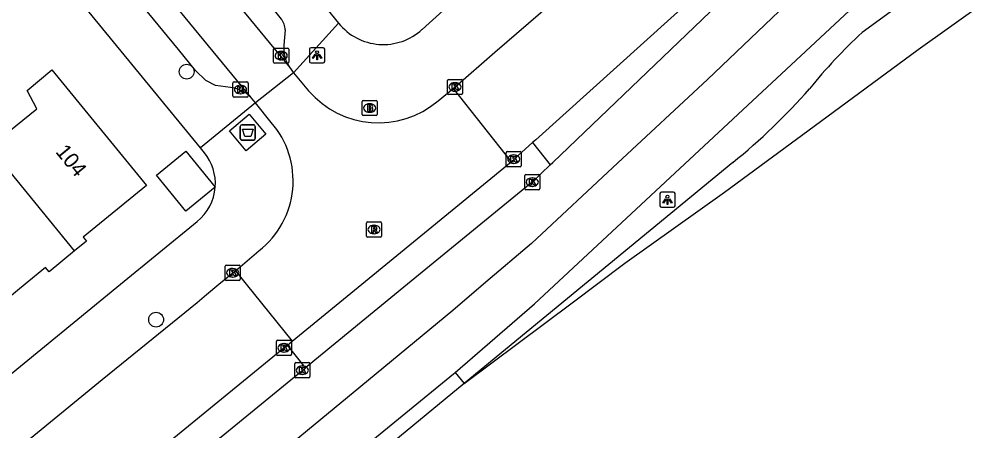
# Model space of a CAD drawing. Extents: x 162074 to 163034, y 381824 to 382557.
# Drawn here: x 162697.9 to 162760.7, y 381990.3 to 382017.5 of the extents above; entities that cross this region are included whole.
import ezdxf

# ---------------------------------------------------------------- set-up
doc = ezdxf.new("R2010")
doc.units = 0
for name, color, linetype in [('IMGEO_Afval_apart_plaats', 7, 'Continuous'), ('IMGEO_Berm_gesloten', 7, 'Continuous'), ('IMGEO_Boom', 7, 'Continuous'), ('IMGEO_Brandkraan', 7, 'Continuous'), ('IMGEO_Haag', 7, 'Continuous'), ('IMGEO_Kolk', 7, 'Continuous'), ('IMGEO_Lichtpunt', 7, 'Continuous'), ('IMGEO_Pand', 7, 'Continuous'), ('IMGEO_Pand_nummerreeks', 7, 'Continuous'), ('IMGEO_Rijbaan_lokaal_open', 7, 'Continuous'), ('IMGEO_Rijbaan_regionaal_gesloten', 7, 'Continuous'), ('IMGEO_Rioolput', 7, 'Continuous'), ('IMGEO_Voetpad_gesloten', 7, 'Continuous'), ('IMGEO_Voetpad_open', 7, 'Continuous')]:
    doc.layers.add(name, color=color, linetype=linetype)

msp = doc.modelspace()

# ---------------------------------------------------------------- linework, layer by layer
at = {"layer": 'IMGEO_Afval_apart_plaats'}
for p, q in [((162712.524, 382009.61), (162712.524, 382010.41)), ((162712.524, 382010.41), (162712.524, 382009.61)), ((162712.624, 382010.51), (162713.414, 382010.51)), ((162713.414, 382010.51), (162712.624, 382010.51)), ((162713.514, 382010.41), (162713.514, 382009.61)), ((162713.514, 382009.61), (162713.514, 382010.41)), ((162713.414, 382009.51), (162712.624, 382009.51)), ((162712.624, 382009.51), (162713.414, 382009.51))]:
    msp.add_line(p, q, dxfattribs=at)
msp.add_lwpolyline([(162712.667, 382010.224), (162713.371, 382010.224), (162713.222, 382009.754), (162712.816, 382009.754), (162712.667, 382010.224)], dxfattribs=at)
for centre, start, end in [((162712.624, 382010.41), 90, 180), ((162712.624, 382010.41), 90, 180), ((162713.414, 382010.41), 0, 90), ((162713.414, 382010.41), 360, 90), ((162712.624, 382009.61), 180, 270), ((162712.624, 382009.61), 180, 270), ((162713.414, 382009.61), 270, 0), ((162713.414, 382009.61), 270, 0)]:
    msp.add_arc(centre, 0.1, start, end, dxfattribs=at)
at = {"layer": 'IMGEO_Berm_gesloten'}
msp.add_lwpolyline([(162726.692, 381994.177), (162727.302, 381993.446)], dxfattribs=at)
at = {"layer": 'IMGEO_Boom'}
for centre in [(162708.988, 382014.019), (162706.974, 381997.662)]:
    msp.add_circle(centre, 0.489, dxfattribs=at)
at = {"layer": 'IMGEO_Brandkraan'}
for p, q in [((162720.634, 382012.122), (162721.486, 382012.122)), ((162720.559, 382011.196), (162720.559, 382012.048)), ((162721.047, 382011.902), (162721.072, 382011.902)), ((162721.56, 382012.048), (162721.56, 382011.196)), ((162721.486, 382011.122), (162720.634, 382011.122)), ((162721.07, 382011.342), (162721.045, 382011.342))]:
    msp.add_line(p, q, dxfattribs=at)
for points in [[(162720.634, 382012.122), (162721.486, 382012.122)], [(162720.559, 382011.196), (162720.559, 382012.048)], [(162720.907, 382011.822), (162720.907, 382011.422), (162721.12, 382011.422)], [(162721.138, 382011.822), (162720.907, 382011.822)], [(162721.086, 382011.741), (162721.032, 382011.741), (162721.032, 382011.665)], [(162721.032, 382011.665), (162721.085, 382011.665)], [(162721.094, 382011.589), (162721.032, 382011.589), (162721.032, 382011.508)], [(162721.032, 382011.508), (162721.094, 382011.508)], [(162721.56, 382012.048), (162721.56, 382011.196)], [(162721.486, 382011.122), (162720.634, 382011.122)]]:
    msp.add_lwpolyline(points, dxfattribs=at)
for centre, radius, start, end in [((162720.636, 382012.046), 0.0765, 91.55205, 178.44795), ((162720.636, 382012.046), 0.0765, 91.55205, 178.44795), ((162721.484, 382012.046), 0.0765, 1.55205, 88.44795), ((162721.484, 382012.046), 0.0765, 1.55205, 88.44795), ((162721.087, 382011.703), 0.0379, 267.82845, 90.93552), ((162721.095, 382011.548), 0.0404, 269.87594, 90.50774), ((162721.126, 382011.673), 0.251, 268.66757, 293.53466), ((162721.142, 382011.677), 0.145, 59.4692, 91.53667), ((162721.167, 382011.724), 0.0922, 285.51372, 58.15012), ((162721.172, 382011.532), 0.105, 301.31148, 78.98903), ((162720.636, 382011.198), 0.0765, 181.55205, 268.44795), ((162720.636, 382011.198), 0.0765, 181.55205, 268.44795), ((162721.484, 382011.198), 0.0765, 271.55205, 358.44795), ((162721.484, 382011.198), 0.0765, 271.55205, 358.44795)]:
    msp.add_arc(centre, radius, start, end, dxfattribs=at)
for centre, major_axis, ratio, start_param, end_param in [((162721.046, 382011.622), (-0.387, 0.002), 0.722429, 4.712389, 7.853982), ((162721.071, 382011.622), (-0.39, 0.002), 0.717154, 1.570796, 4.712389)]:
    msp.add_ellipse(centre, major_axis=major_axis, ratio=ratio, start_param=start_param, end_param=end_param, dxfattribs=at)
at = {"layer": 'IMGEO_Haag'}
for points in [[(162731.798, 382009.34), (162732.963, 382007.864)], [(162716.816, 381994.492), (162715.639, 381995.982)]]:
    msp.add_lwpolyline(points, dxfattribs=at)
at = {"layer": 'IMGEO_Kolk'}
for p, q in [((162714.723, 382014.649), (162714.723, 382015.501)), ((162714.798, 382015.575), (162715.65, 382015.575)), ((162715.211, 382015.355), (162715.236, 382015.355)), ((162715.724, 382015.501), (162715.724, 382014.649)), ((162715.65, 382014.575), (162714.798, 382014.575)), ((162715.234, 382014.795), (162715.209, 382014.795)), ((162712.11, 382013.344), (162712.962, 382013.344)), ((162726.188, 382012.588), (162726.188, 382013.44)), ((162726.263, 382013.514), (162727.115, 382013.514)), ((162727.189, 382013.44), (162727.189, 382012.588)), ((162712.035, 382012.418), (162712.035, 382013.27)), ((162712.523, 382013.124), (162712.548, 382013.124)), ((162713.036, 382013.27), (162713.036, 382012.418)), ((162726.699, 382012.734), (162726.674, 382012.734)), ((162726.676, 382013.294), (162726.701, 382013.294)), ((162712.962, 382012.344), (162712.11, 382012.344)), ((162712.546, 382012.564), (162712.521, 382012.564)), ((162727.115, 382012.514), (162726.263, 382012.514)), ((162730.06, 382007.819), (162730.06, 382008.671)), ((162730.135, 382008.745), (162730.987, 382008.745)), ((162730.548, 382008.525), (162730.573, 382008.525)), ((162731.061, 382008.671), (162731.061, 382007.819)), ((162730.987, 382007.745), (162730.135, 382007.745)), ((162730.571, 382007.965), (162730.546, 382007.965)), ((162731.284, 382006.309), (162731.284, 382007.161)), ((162731.359, 382007.235), (162732.211, 382007.235)), ((162732.285, 382007.161), (162732.285, 382006.309)), ((162731.795, 382006.455), (162731.77, 382006.455)), ((162731.772, 382007.015), (162731.797, 382007.015)), ((162732.211, 382006.235), (162731.359, 382006.235)), ((162711.524, 382000.329), (162711.524, 382001.181)), ((162711.599, 382001.255), (162712.451, 382001.255)), ((162712.012, 382001.035), (162712.037, 382001.035)), ((162712.525, 382001.181), (162712.525, 382000.329)), ((162712.451, 382000.255), (162711.599, 382000.255)), ((162712.035, 382000.475), (162712.01, 382000.475)), ((162714.904, 381995.376), (162714.904, 381996.228)), ((162714.979, 381996.302), (162715.831, 381996.302)), ((162715.392, 381996.082), (162715.417, 381996.082)), ((162715.905, 381996.228), (162715.905, 381995.376)), ((162715.831, 381995.302), (162714.979, 381995.302)), ((162715.415, 381995.522), (162715.39, 381995.522)), ((162716.114, 381993.902), (162716.114, 381994.754)), ((162716.189, 381994.828), (162717.041, 381994.828)), ((162716.602, 381994.608), (162716.627, 381994.608)), ((162717.115, 381994.754), (162717.115, 381993.902)), ((162716.625, 381994.048), (162716.6, 381994.048)), ((162717.041, 381993.828), (162716.189, 381993.828))]:
    msp.add_line(p, q, dxfattribs=at)
for points in [[(162714.723, 382014.649), (162714.723, 382015.501)], [(162714.798, 382015.575), (162715.65, 382015.575)], [(162715.044, 382015.275), (162715.167, 382015.275), (162715.167, 382015.124), (162715.297, 382015.275), (162715.461, 382015.275), (162715.315, 382015.124), (162715.468, 382014.875), (162715.316, 382014.875), (162715.231, 382015.039), (162715.167, 382014.972), (162715.167, 382014.875), (162715.044, 382014.875), (162715.044, 382015.275)], [(162715.724, 382015.501), (162715.724, 382014.649)], [(162715.65, 382014.575), (162714.798, 382014.575)], [(162712.11, 382013.344), (162712.962, 382013.344)], [(162726.188, 382012.588), (162726.188, 382013.44)], [(162726.263, 382013.514), (162727.115, 382013.514)], [(162727.189, 382013.44), (162727.189, 382012.588)], [(162712.035, 382012.418), (162712.035, 382013.27)], [(162712.356, 382013.044), (162712.479, 382013.044), (162712.479, 382012.893), (162712.609, 382013.044), (162712.773, 382013.044), (162712.627, 382012.893), (162712.78, 382012.644), (162712.628, 382012.644), (162712.543, 382012.808), (162712.479, 382012.741), (162712.479, 382012.644), (162712.356, 382012.644), (162712.356, 382013.044)], [(162713.036, 382013.27), (162713.036, 382012.418)], [(162726.509, 382013.214), (162726.632, 382013.214), (162726.632, 382013.063), (162726.762, 382013.214), (162726.926, 382013.214), (162726.78, 382013.063), (162726.933, 382012.814), (162726.781, 382012.814), (162726.696, 382012.978), (162726.632, 382012.911), (162726.632, 382012.814), (162726.509, 382012.814), (162726.509, 382013.214)], [(162712.962, 382012.344), (162712.11, 382012.344)], [(162727.115, 382012.514), (162726.263, 382012.514)], [(162730.06, 382007.819), (162730.06, 382008.671)], [(162730.135, 382008.745), (162730.987, 382008.745)], [(162730.381, 382008.445), (162730.504, 382008.445), (162730.504, 382008.294), (162730.634, 382008.445), (162730.798, 382008.445), (162730.652, 382008.294), (162730.805, 382008.045), (162730.653, 382008.045), (162730.568, 382008.209), (162730.504, 382008.142), (162730.504, 382008.045), (162730.381, 382008.045), (162730.381, 382008.445)], [(162731.061, 382008.671), (162731.061, 382007.819)], [(162730.987, 382007.745), (162730.135, 382007.745)], [(162731.284, 382006.309), (162731.284, 382007.161)], [(162731.359, 382007.235), (162732.211, 382007.235)], [(162732.285, 382007.161), (162732.285, 382006.309)], [(162731.605, 382006.935), (162731.728, 382006.935), (162731.728, 382006.784), (162731.858, 382006.935), (162732.022, 382006.935), (162731.876, 382006.784), (162732.029, 382006.535), (162731.877, 382006.535), (162731.792, 382006.699), (162731.728, 382006.632), (162731.728, 382006.535), (162731.605, 382006.535), (162731.605, 382006.935)], [(162732.211, 382006.235), (162731.359, 382006.235)], [(162711.524, 382000.329), (162711.524, 382001.181)], [(162711.599, 382001.255), (162712.451, 382001.255)], [(162711.845, 382000.955), (162711.968, 382000.955), (162711.968, 382000.804), (162712.098, 382000.955), (162712.262, 382000.955), (162712.116, 382000.804), (162712.269, 382000.555), (162712.117, 382000.555), (162712.032, 382000.719), (162711.968, 382000.652), (162711.968, 382000.555), (162711.845, 382000.555), (162711.845, 382000.955)], [(162712.525, 382001.181), (162712.525, 382000.329)], [(162712.451, 382000.255), (162711.599, 382000.255)], [(162714.904, 381995.376), (162714.904, 381996.228)], [(162714.979, 381996.302), (162715.831, 381996.302)], [(162715.225, 381996.002), (162715.348, 381996.002), (162715.348, 381995.851), (162715.478, 381996.002), (162715.642, 381996.002), (162715.496, 381995.851), (162715.649, 381995.602), (162715.497, 381995.602), (162715.412, 381995.766), (162715.348, 381995.699), (162715.348, 381995.602), (162715.225, 381995.602), (162715.225, 381996.002)], [(162715.905, 381996.228), (162715.905, 381995.376)], [(162715.831, 381995.302), (162714.979, 381995.302)], [(162716.114, 381993.902), (162716.114, 381994.754)], [(162716.189, 381994.828), (162717.041, 381994.828)], [(162716.435, 381994.528), (162716.558, 381994.528), (162716.558, 381994.377), (162716.688, 381994.528), (162716.852, 381994.528), (162716.706, 381994.377), (162716.859, 381994.128), (162716.707, 381994.128), (162716.622, 381994.292), (162716.558, 381994.225), (162716.558, 381994.128), (162716.435, 381994.128), (162716.435, 381994.528)], [(162717.115, 381994.754), (162717.115, 381993.902)], [(162717.041, 381993.828), (162716.189, 381993.828)]]:
    msp.add_lwpolyline(points, dxfattribs=at)
for centre, start, end in [((162714.8, 382015.499), 91.55205, 178.44795), ((162714.8, 382015.499), 91.55205, 178.44795), ((162715.648, 382015.499), 1.55205, 88.44795), ((162715.648, 382015.499), 1.55205, 88.44795), ((162714.8, 382014.651), 181.55205, 268.44795), ((162714.8, 382014.651), 181.55205, 268.44795), ((162715.648, 382014.651), 271.55205, 358.44795), ((162715.648, 382014.651), 271.55205, 358.44795), ((162712.112, 382013.268), 91.55205, 178.44795), ((162712.112, 382013.268), 91.55205, 178.44795), ((162712.96, 382013.268), 1.55205, 88.44795), ((162712.96, 382013.268), 1.55205, 88.44795), ((162726.265, 382013.438), 91.55205, 178.44795), ((162726.265, 382013.438), 91.55205, 178.44795), ((162727.113, 382013.438), 1.55205, 88.44795), ((162727.113, 382013.438), 1.55205, 88.44795), ((162712.112, 382012.42), 181.55205, 268.44795), ((162712.112, 382012.42), 181.55205, 268.44795), ((162712.96, 382012.42), 271.55205, 358.44795), ((162712.96, 382012.42), 271.55205, 358.44795), ((162726.265, 382012.59), 181.55205, 268.44795), ((162726.265, 382012.59), 181.55205, 268.44795), ((162727.113, 382012.59), 271.55205, 358.44795), ((162727.113, 382012.59), 271.55205, 358.44795), ((162730.137, 382008.669), 91.55205, 178.44795), ((162730.137, 382008.669), 91.55205, 178.44795), ((162730.985, 382008.669), 1.55205, 88.44795), ((162730.985, 382008.669), 1.55205, 88.44795), ((162730.137, 382007.821), 181.55205, 268.44795), ((162730.137, 382007.821), 181.55205, 268.44795), ((162730.985, 382007.821), 271.55205, 358.44795), ((162730.985, 382007.821), 271.55205, 358.44795), ((162731.361, 382007.159), 91.55205, 178.44795), ((162731.361, 382007.159), 91.55205, 178.44795), ((162732.209, 382007.159), 1.55205, 88.44795), ((162732.209, 382007.159), 1.55205, 88.44795), ((162731.361, 382006.311), 181.55205, 268.44795), ((162731.361, 382006.311), 181.55205, 268.44795), ((162732.209, 382006.311), 271.55205, 358.44795), ((162732.209, 382006.311), 271.55205, 358.44795), ((162711.601, 382001.179), 91.55205, 178.44795), ((162711.601, 382001.179), 91.55205, 178.44795), ((162712.449, 382001.179), 1.55205, 88.44795), ((162712.449, 382001.179), 1.55205, 88.44795), ((162711.601, 382000.331), 181.55205, 268.44795), ((162711.601, 382000.331), 181.55205, 268.44795), ((162712.449, 382000.331), 271.55205, 358.44795), ((162712.449, 382000.331), 271.55205, 358.44795), ((162714.981, 381996.226), 91.55205, 178.44795), ((162714.981, 381996.226), 91.55205, 178.44795), ((162715.829, 381996.226), 1.55205, 88.44795), ((162715.829, 381996.226), 1.55205, 88.44795), ((162714.981, 381995.378), 181.55205, 268.44795), ((162714.981, 381995.378), 181.55205, 268.44795), ((162715.829, 381995.378), 271.55205, 358.44795), ((162715.829, 381995.378), 271.55205, 358.44795), ((162716.191, 381994.752), 91.55205, 178.44795), ((162716.191, 381994.752), 91.55205, 178.44795), ((162717.039, 381994.752), 1.55205, 88.44795), ((162717.039, 381994.752), 1.55205, 88.44795), ((162716.191, 381993.904), 181.55205, 268.44795), ((162716.191, 381993.904), 181.55205, 268.44795), ((162717.039, 381993.904), 271.55205, 358.44795), ((162717.039, 381993.904), 271.55205, 358.44795)]:
    msp.add_arc(centre, 0.0765, start, end, dxfattribs=at)
for centre, major_axis, ratio, start_param, end_param in [((162715.21, 382015.075), (-0.387, 0.002), 0.722429, 4.712389, 7.853982), ((162715.235, 382015.075), (-0.39, 0.002), 0.717154, 1.570796, 4.712389), ((162712.522, 382012.844), (-0.387, 0.002), 0.722429, 4.712389, 7.853982), ((162712.547, 382012.844), (-0.39, 0.002), 0.717154, 1.570796, 4.712389), ((162726.675, 382013.014), (-0.387, 0.002), 0.722429, 4.712389, 7.853982), ((162726.7, 382013.014), (-0.39, 0.002), 0.717154, 1.570796, 4.712389), ((162730.547, 382008.245), (-0.387, 0.002), 0.722429, 4.712389, 7.853982), ((162730.572, 382008.245), (-0.39, 0.002), 0.717154, 1.570796, 4.712389), ((162731.771, 382006.735), (-0.387, 0.002), 0.722429, 4.712389, 7.853982), ((162731.796, 382006.735), (-0.39, 0.002), 0.717154, 1.570796, 4.712389), ((162712.011, 382000.755), (-0.387, 0.002), 0.722429, 4.712389, 7.853982), ((162712.036, 382000.755), (-0.39, 0.002), 0.717154, 1.570796, 4.712389), ((162715.391, 381995.802), (-0.387, 0.002), 0.722429, 4.712389, 7.853982), ((162715.416, 381995.802), (-0.39, 0.002), 0.717154, 1.570796, 4.712389), ((162716.601, 381994.328), (-0.387, 0.002), 0.722429, 4.712389, 7.853982), ((162716.626, 381994.328), (-0.39, 0.002), 0.717154, 1.570796, 4.712389)]:
    msp.add_ellipse(centre, major_axis=major_axis, ratio=ratio, start_param=start_param, end_param=end_param, dxfattribs=at)
at = {"layer": 'IMGEO_Lichtpunt'}
for p, q in [((162717.095, 382015.507), (162717.095, 382014.7)), ((162717.095, 382015.507), (162717.095, 382014.7)), ((162717.997, 382015.602), (162717.189, 382015.602)), ((162717.997, 382015.602), (162717.189, 382015.602)), ((162718.091, 382014.7), (162718.091, 382015.507)), ((162718.091, 382014.7), (162718.091, 382015.507)), ((162717.189, 382014.606), (162717.997, 382014.606)), ((162717.189, 382014.606), (162717.997, 382014.606)), ((162740.205, 382005.973), (162740.205, 382005.166)), ((162740.205, 382005.973), (162740.205, 382005.166)), ((162741.107, 382006.068), (162740.299, 382006.068)), ((162741.107, 382006.068), (162740.299, 382006.068)), ((162741.201, 382005.166), (162741.201, 382005.973)), ((162741.201, 382005.166), (162741.201, 382005.973)), ((162740.299, 382005.072), (162741.107, 382005.072)), ((162740.299, 382005.072), (162741.107, 382005.072))]:
    msp.add_line(p, q, dxfattribs=at)
for points in [[(162717.469, 382015.171), (162717.508, 382015.143), (162717.32, 382014.881), (162717.282, 382014.908), (162717.469, 382015.171)], [(162717.571, 382015.123), (162717.618, 382015.123), (162717.618, 382014.801), (162717.571, 382014.801), (162717.571, 382015.123)], [(162717.681, 382015.143), (162717.719, 382015.17), (162717.906, 382014.908), (162717.867, 382014.88), (162717.681, 382015.143)], [(162740.579, 382005.637), (162740.618, 382005.609), (162740.43, 382005.347), (162740.392, 382005.374), (162740.579, 382005.637)], [(162740.681, 382005.589), (162740.728, 382005.589), (162740.728, 382005.267), (162740.681, 382005.267), (162740.681, 382005.589)], [(162740.791, 382005.609), (162740.829, 382005.636), (162741.016, 382005.374), (162740.977, 382005.346), (162740.791, 382005.609)]]:
    msp.add_lwpolyline(points, dxfattribs=at)
for centre in [(162717.594, 382015.305), (162740.704, 382005.771)]:
    msp.add_circle(centre, 0.0994, dxfattribs=at)
for centre, start, end in [((162717.189, 382015.507), 90, 180), ((162717.189, 382015.507), 90, 180), ((162717.997, 382015.507), 0, 90), ((162717.997, 382015.507), 0, 90), ((162717.189, 382014.7), 180, 270), ((162717.189, 382014.7), 180, 270), ((162717.997, 382014.7), 270, 0), ((162717.997, 382014.7), 270, 360), ((162740.299, 382005.973), 90, 180), ((162740.299, 382005.973), 90, 180), ((162741.107, 382005.973), 0, 90), ((162741.107, 382005.973), 0, 90), ((162740.299, 382005.166), 180, 270), ((162740.299, 382005.166), 180, 270), ((162741.107, 382005.166), 270, 0), ((162741.107, 382005.166), 270, 360)]:
    msp.add_arc(centre, 0.0946, start, end, dxfattribs=at)
at = {"layer": 'IMGEO_Pand'}
for points in [[(162695.172, 382010.058), (162695.973, 382010.713), (162696.798, 382009.704), (162699.098, 382011.568), (162698.468, 382012.777), (162700.104, 382014.134), (162706.33, 382006.516), (162702.161, 382003.108), (162702.38, 382002.84), (162701.596, 382002.199)], [(162701.596, 382002.199), (162695.172, 382010.058)], [(162710.873, 382006.4), (162708.937, 382004.818), (162707.001, 382007.187), (162708.937, 382008.769), (162710.873, 382006.4)], [(162701.596, 382002.199), (162699.909, 382000.82), (162699.684, 382001.095), (162698.344, 382000), (162696.535, 381998.521)]]:
    msp.add_lwpolyline(points, dxfattribs=at)
at = {"layer": 'IMGEO_Rijbaan_lokaal_open'}
for points in [[(162726.574, 382012.905), (162726.69, 382013.012), (162729.315, 382015.305), (162734.558, 382019.836), (162740.88, 382025.429), (162744.085, 382028.233)], [(162750.053, 382025.788), (162732.012, 382009.534), (162731.798, 382009.34)], [(162706.905, 382025.098), (162715.769, 382014.327)], [(162713.195, 382012.363), (162704.082, 382023.46)], [(162716.034, 382013.954), (162713.526, 382011.966)], [(162715.769, 382014.327), (162716.034, 382013.954)], [(162716.034, 382013.954), (162717.027, 382012.754)], [(162725.571, 382012.101), (162726.574, 382012.905)], [(162726.574, 382012.905), (162730.391, 382008.073)], [(162713.526, 382011.966), (162713.195, 382012.363)], [(162714.564, 382010.666), (162713.526, 382011.966)], [(162730.391, 382008.073), (162731.798, 382009.34)], [(162715.956, 381996.242), (162720.549, 382000), (162730.391, 382008.073)], [(162712.201, 382000.888), (162713.757, 382002.205)], [(162667.27, 381964.158), (162668.056, 381964.746), (162703.423, 381993.708), (162709.685, 381998.798), (162710.3, 381999.325), (162711.115, 382000), (162712.025, 382000.754), (162712.201, 382000.888)], [(162712.201, 382000.888), (162712.918, 382000), (162715.956, 381996.242)], [(162715.639, 381995.982), (162672.356, 381960.57)], [(162715.639, 381995.982), (162715.956, 381996.242)]]:
    msp.add_lwpolyline(points, dxfattribs=at)
for centre, radius, start, end in [((162721.627, 382016.723), 6.076, 220.78981, 310.46919), ((162710.165, 382006.817), 5.846, 307.91698, 41.18638)]:
    msp.add_arc(centre, radius, start, end, dxfattribs=at)
at = {"layer": 'IMGEO_Rijbaan_regionaal_gesloten'}
for points in [[(162769.492, 382038.496), (162763.389, 382032.664), (162757.636, 382027.166), (162754.789, 382024.377), (162749.013, 382018.928), (162743.336, 382013.499), (162737.438, 382008.003), (162731.726, 382002.679), (162728.73, 382000.13), (162726.543, 381998.269), (162720.477, 381993.259), (162714.322, 381988.176), (162711.181, 381985.616), (162709.59, 381984.248), (162678.587, 381958.753)], [(162726.692, 381994.177), (162731.928, 381998.712), (162753.027, 382018.342), (162770.462, 382035.069), (162772.059, 382036.498)], [(162775.869, 382032.852), (162753.538, 382016.6)], [(162727.302, 381993.446), (162734.416, 381998.779), (162737.897, 382001.398), (162744.462, 382006.076), (162750.794, 382010.733), (162757.246, 382015.477), (162763.753, 382020.148), (162769.758, 382024.585), (162776.979, 382029.804)], [(162732.963, 382007.864), (162733.142, 382008.036), (162750.779, 382024.936)], [(162732.963, 382007.864), (162731.772, 382006.723), (162723.552, 382000), (162716.816, 381994.492)], [(162745.011, 382008.024), (162727.302, 381993.446)], [(162667.888, 381946.191), (162710.994, 381981.337), (162726.582, 381994.087), (162726.692, 381994.177)], [(162673.553, 381959.11), (162716.816, 381994.492)], [(162727.302, 381993.446), (162715.499, 381983.729), (162667.507, 381944.555), (162661.482, 381939.678), (162659.417, 381938.007), (162655.422, 381934.783), (162648.628, 381929.257), (162641.585, 381923.497), (162635.551, 381918.548), (162595.373, 381885.446), (162590.613, 381881.492), (162585.447, 381877.124)]]:
    msp.add_lwpolyline(points, dxfattribs=at)
for centre, radius, start, end in [((162777.45, 381990.813), 35.168, 132.83919, 141.09744), ((162718.254, 382040.937), 42.417, 309.10938, 318.62098)]:
    msp.add_arc(centre, radius, start, end, dxfattribs=at)
at = {"layer": 'IMGEO_Rioolput'}
for p, q in [((162720.847, 382003.18), (162720.847, 382004.032)), ((162720.922, 382004.106), (162721.774, 382004.106)), ((162721.848, 382004.032), (162721.848, 382003.18)), ((162721.358, 382003.326), (162721.333, 382003.326)), ((162721.335, 382003.886), (162721.36, 382003.886)), ((162721.774, 382003.106), (162720.922, 382003.106))]:
    msp.add_line(p, q, dxfattribs=at)
for points in [[(162720.847, 382003.18), (162720.847, 382004.032)], [(162720.922, 382004.106), (162721.774, 382004.106)], [(162721.848, 382004.032), (162721.848, 382003.18)], [(162721.436, 382003.804), (162721.184, 382003.806), (162721.184, 382003.406)], [(162721.184, 382003.406), (162721.308, 382003.406), (162721.308, 382003.568), (162721.319, 382003.568)], [(162721.362, 382003.725), (162721.308, 382003.725), (162721.308, 382003.644)], [(162721.308, 382003.644), (162721.36, 382003.644)], [(162721.366, 382003.539), (162721.437, 382003.406), (162721.577, 382003.406), (162721.512, 382003.532)], [(162721.774, 382003.106), (162720.922, 382003.106)]]:
    msp.add_lwpolyline(points, dxfattribs=at)
for centre, radius, start, end in [((162720.924, 382004.03), 0.0765, 91.55205, 178.44795), ((162720.924, 382004.03), 0.0765, 91.55205, 178.44795), ((162721.772, 382004.03), 0.0765, 1.55205, 88.44795), ((162721.772, 382004.03), 0.0765, 1.55205, 88.44795), ((162721.318, 382003.515), 0.0533, 26.02933, 88.69889), ((162721.344, 382003.833), 0.19, 274.7715, 282.96867), ((162721.368, 382003.629), 0.0964, 77.00612, 93.18647), ((162721.382, 382003.686), 0.0378, 276.66336, 79.67722), ((162721.435, 382003.694), 0.109, 350.36119, 89.41601), ((162721.433, 382003.694), 0.112, 277.58423, 350.98172), ((162721.417, 382003.479), 0.108, 29.51342, 73.79051), ((162720.924, 382003.182), 0.0765, 181.55205, 268.44795), ((162720.924, 382003.182), 0.0765, 181.55205, 268.44795), ((162721.772, 382003.182), 0.0765, 271.55205, 358.44795), ((162721.772, 382003.182), 0.0765, 271.55205, 358.44795)]:
    msp.add_arc(centre, radius, start, end, dxfattribs=at)
for centre, major_axis, ratio, start_param, end_param in [((162721.334, 382003.606), (-0.387, 0.002), 0.722429, 4.712389, 7.853982), ((162721.359, 382003.606), (-0.39, 0.002), 0.717154, 1.570796, 4.712389)]:
    msp.add_ellipse(centre, major_axis=major_axis, ratio=ratio, start_param=start_param, end_param=end_param, dxfattribs=at)
at = {"layer": 'IMGEO_Voetpad_gesloten'}
msp.add_lwpolyline([(162711.818, 382010.118), (162713.121, 382011.21), (162714.219, 382009.9), (162712.916, 382008.808), (162711.818, 382010.118)], dxfattribs=at)
at = {"layer": 'IMGEO_Voetpad_open'}
for points in [[(162709.893, 382008.991), (162697.016, 382024.713), (162697.896, 382025.512), (162662.101, 382069.449), (162657.097, 382075.079), (162644.151, 382088.188), (162639.153, 382092.704), (162629.902, 382100.628)], [(162724.511, 382016.802), (162741.397, 382032.094), (162754.763, 382044.439), (162765.79, 382055.945)], [(162704.906, 382034.553), (162719.013, 382017.214)], [(162709.781, 382023.902), (162713.543, 382019.301), (162714.516, 382018.364), (162715.224, 382017.493)], [(162711.875, 382012.981), (162710.884, 382013.099), (162710.261, 382013.427), (162709.572, 382014.104), (162708.457, 382015.49), (162704.733, 382020.002)], [(162719.013, 382017.214), (162716.034, 382013.954)], [(162715.495, 382016.771), (162715.406, 382015.778)], [(162713.526, 382011.966), (162709.893, 382008.991)], [(162710.156, 382008.67), (162709.893, 382008.991)], [(162663.669, 381966.433), (162704.626, 382000), (162709.684, 382004.145)]]:
    msp.add_lwpolyline(points, dxfattribs=at)
for centre, radius, start, end in [((162714.233, 382016.709), 1.263, 2.80417, 38.3427), ((162721.956, 382019.598), 3.787, 219.00561, 312.42334), ((162717.57, 382015.548), 2.176, 173.94477, 214.1463), ((162711.635, 382010.751), 2.243, 45.95478, 83.86895), ((162707.688, 382006.642), 3.194, 355.64759, 39.4108), ((162707.684, 382006.64), 3.198, 308.70637, 355.69071)]:
    msp.add_arc(centre, radius, start, end, dxfattribs=at)

# ---------------------------------------------------------------- texts
at = {"layer": 'IMGEO_Pand_nummerreeks'}
msp.add_text('104', height=1, rotation=309.25827, dxfattribs=at).set_placement((162700.293, 382008.719))

doc.saveas('drawing.dxf')
